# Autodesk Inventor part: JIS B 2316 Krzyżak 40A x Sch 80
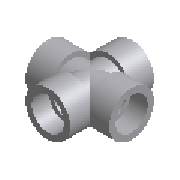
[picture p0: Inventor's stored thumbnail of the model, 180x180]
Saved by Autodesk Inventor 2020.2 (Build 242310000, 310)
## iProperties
Manager: www.cadconsulting.pl
Company: Fabian Stasiak CAD Consulting
NAME: PIPING: JIS B 2316 Cross
DATA: <meta><inlinegroups number="2" deflen="4.62"></inlinegroups><connections number="4"></connections><angles><a>1.57079632679489</a><a>3.14159265358979</a><a>1.570
Created: 2014-02
Part Number: JIS B 2316 Krzyżak 40A x Sch 80
Material: Stal
Description: Krzyżak
Document SubType Name: Modeling
Standard: JIS B 2316
Designer: F.Stasiak
Standards Organization: JIS
Language: pl-PL
Size Designation: 40A x Sch 80
Categories: <MemberInstance><Categories><Category DisplayName="Rury cienko- i grubościenne" InternalName="4347fa0f-2144-441d-94cd-e3e15c92b736" Mnemonic="TUBEANDPIPE"><Cate
Density: 1 g/cm^3
Appearance: Płyta
Catalog Web Link: www.expertbooks.pl
IsCustomPart: 0
Author: F.Stasiak
Subject: Zbiór ćwiczeń. Autodesk Inventor 2020. Kurs Professional
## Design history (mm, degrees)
sketch "Sketch1"
  geometry: L1 (0, 0)-(44.5, 0); L2 (44.5, 0)-(44.5, 26.2); L3 (18.3, 30.15)-(0, 30.15); L4 (0, 24.55)-(0, 0); L5 (12.7, 24.55)-(12.7, 20.6); L6 (12.7, 20.6)-(44.5, 20.6); L7 (18.3, 30.15)-(18.3, 26.2); L8 (18.3, 26.2)-(44.5, 26.2); L9 (0, 24.55)-(0, 30.15); L10 (76.3, 20.6)-(44.5, 20.6); L11 (89, 24.55)-(89, 30.15); L12 (70.7, 30.15)-(89, 30.15); L13 (70.7, 30.15)-(70.7, 26.2); L14 (70.7, 26.2)-(44.5, 26.2); L15 (89, 24.55)-(89, 0); L16 (89, 0)-(44.5, 0); L17 (0, 24.55)-(12.7, 24.55); L18 (89, 24.55)-(76.3, 24.55); L19 (76.3, 24.55)-(76.3, 20.6); L20 (0, 24.55)-(0, 0); L21 (0, 0)-(89, 0); L22 (89, 0)-(89, 24.55); L23 (12.7, 20.6)-(12.7, 0); L24 (76.3, 20.6)-(76.3, 0); C1 r 2.8 at (15.5, 27.35); C2 r 2.8 at (15.5, 23.4)
  constraints: 48 end point, 7 perpendicular, 7 symmetric about line, 7 tangent, 4 parallel, 3 point on line, 2 centre point, 2 horizontal, 1 collinear, 1 equal radius, 9 other
  dimensions: "d0" = 41.2 diameter of L6 L1 (= D); "d1" = 12.7 distance between parallel lines of L9 L5 (= C1); "d2" = 31.8 distance between parallel lines of L2 L5 (= G); "d6" = 49.1 diameter of L4.start L1 (= S); "d7" = 5.6 distance of L4.start L3.end (= T)
revolve "Revolve1" stored, may be unused: angle "d8" = 90 deg
sketch "Sketch2"
  geometry: L1 (0, 0)-(-44.5, 0) reference; L2 (-44.5, 0)-(-44.5, 44.5); L3 (-44.5, 44.5)-(-69.05, 44.5); L4 (-74.65, 44.5)-(-74.65, 26.2); L5 (-65.1, 0)-(-44.5, 0); L6 (-69.05, 31.8)-(-65.1, 31.8); L7 (-65.1, 31.8)-(-65.1, 0); L8 (-69.05, 44.5)-(-74.65, 44.5); L9 (-74.65, 26.2)-(-70.7, 26.2); L10 (-70.7, 26.2)-(-70.7, 0); L11 (-65.1, 0)-(-70.7, 0); L12 (-69.05, 44.5)-(-69.05, 31.8); L13 (-69.05, 44.5)-(-44.5, 44.5); L14 (-44.5, 44.5)-(-44.5, 0); L15 (-44.5, 0)-(-65.1, 0); L16 (-44.5, -44.5)-(-69.05, -44.5); L17 (-74.65, -44.5)-(-74.65, -26.2); L18 (-69.05, -44.5)-(-74.65, -44.5); L19 (-69.05, -44.5)-(-69.05, -31.8); L20 (-69.05, -44.5)-(-44.5, -44.5); L21 (-69.05, -31.8)-(-65.1, -31.8); L22 (-74.65, -26.2)-(-70.7, -26.2); L23 (-70.7, -26.2)-(-70.7, 0); L24 (-44.5, 0)-(-44.5, -44.5); L25 (-44.5, -44.5)-(-44.5, 0); L26 (-65.1, -31.8)-(-65.1, 0); L27 (-65.1, -31.8)-(-44.5, -31.8); L28 (-65.1, 31.8)-(-44.5, 31.8); C1 r 2.8 at (-71.85, 29); C2 r 2.8 at (-67.9, 29); C3 r 2.8 at (-71.85, -29); C4 r 2.8 at (-67.9, -29)
  constraints: 54 end point, 9 symmetric about line, 8 perpendicular, 8 tangent, 4 centre point, 2 parallel, 2 point on line, 1 vertical, 13 other
  dimensions: "d3" = 41.2 diameter of L7 L2 (= D); "d4" = 12.7 distance between parallel lines of L6 L8 (= C1); "d5" = 31.8 distance between parallel lines of L6 L5 (= G); "d9" = 49.1 diameter of L3.end L2 (= S); "d10" = 5.6 distance of L3.end L4.start (= T)
revolve "Revolve2" stored, may be unused: angle "d18" = 90 deg
revolve "Revolve3" stored, may be unused: angle "d57" = 90 deg
revolve "Revolve4" stored, may be unused: angle "d58" = 90 deg
workpoint "Work Point1"
workpoint "Work Point2"
workpoint "Work Point3"
workpoint "Work Point4"
workaxis "Work Axis1"
workpoint "Work Point5"
workaxis "Work Axis2"
workpoint "Work Point6"
workaxis "Work Axis3"
workpoint "Work Point7"
workaxis "Work Axis4"
workpoint "Work Point8"
body "Solid1"
other parameters: "S" = 49.1 [user parameter; used in 2 equation terms], "D" = 41.2 [user parameter; used in 2 equation terms], "T" = 5.6 [user parameter; used in 2 equation terms], "C1" = 12.7 [user parameter; used in 2 equation terms], "G" = 31.8 [user parameter; used in 2 equation terms], "Size_Designation" = 12.345 [user parameter]
